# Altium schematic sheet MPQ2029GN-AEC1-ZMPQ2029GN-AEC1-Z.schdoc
size 127 x 101 mm
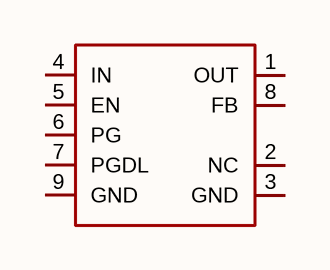
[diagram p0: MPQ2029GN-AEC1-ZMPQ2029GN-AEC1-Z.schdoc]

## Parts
U?  mpq2029gn-aec1-z  [ESOP-8_L4.9-W3.9-P1.27-LS6.0-BL-EP-1]  (value not drawn)

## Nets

Not connected (* = marked no-connect by the designer): U? 1(OUT) 2(NC) 3(GND) 4(IN) 5(EN) 6(PG) 7(PGDL) 8(FB) 9(GND)

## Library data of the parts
U? = mpq2029gn-aec1-z: 输出极性:正极;工作电压:40V;输出电压:1.25V~15V;输出电流:450mA;电源纹波抑制比(PSRR):51dB@(100kHz);输出类型:可调;; Manufacturer: MPS(芯源); AddInBom: yes; ModelId: 1edf17d9e1eb44b9aabe355eb95382d1; ModelTransform: 192.913,236.22,0,0,0,0,0,0,0; Output Configuration: 正极; Voltage - Supply: 40V; Output Current: 450mA; Voltage Dropout: 200mV@(150mA); standby current: 10uA; Output Type: 可调; Number of Outputs: 1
